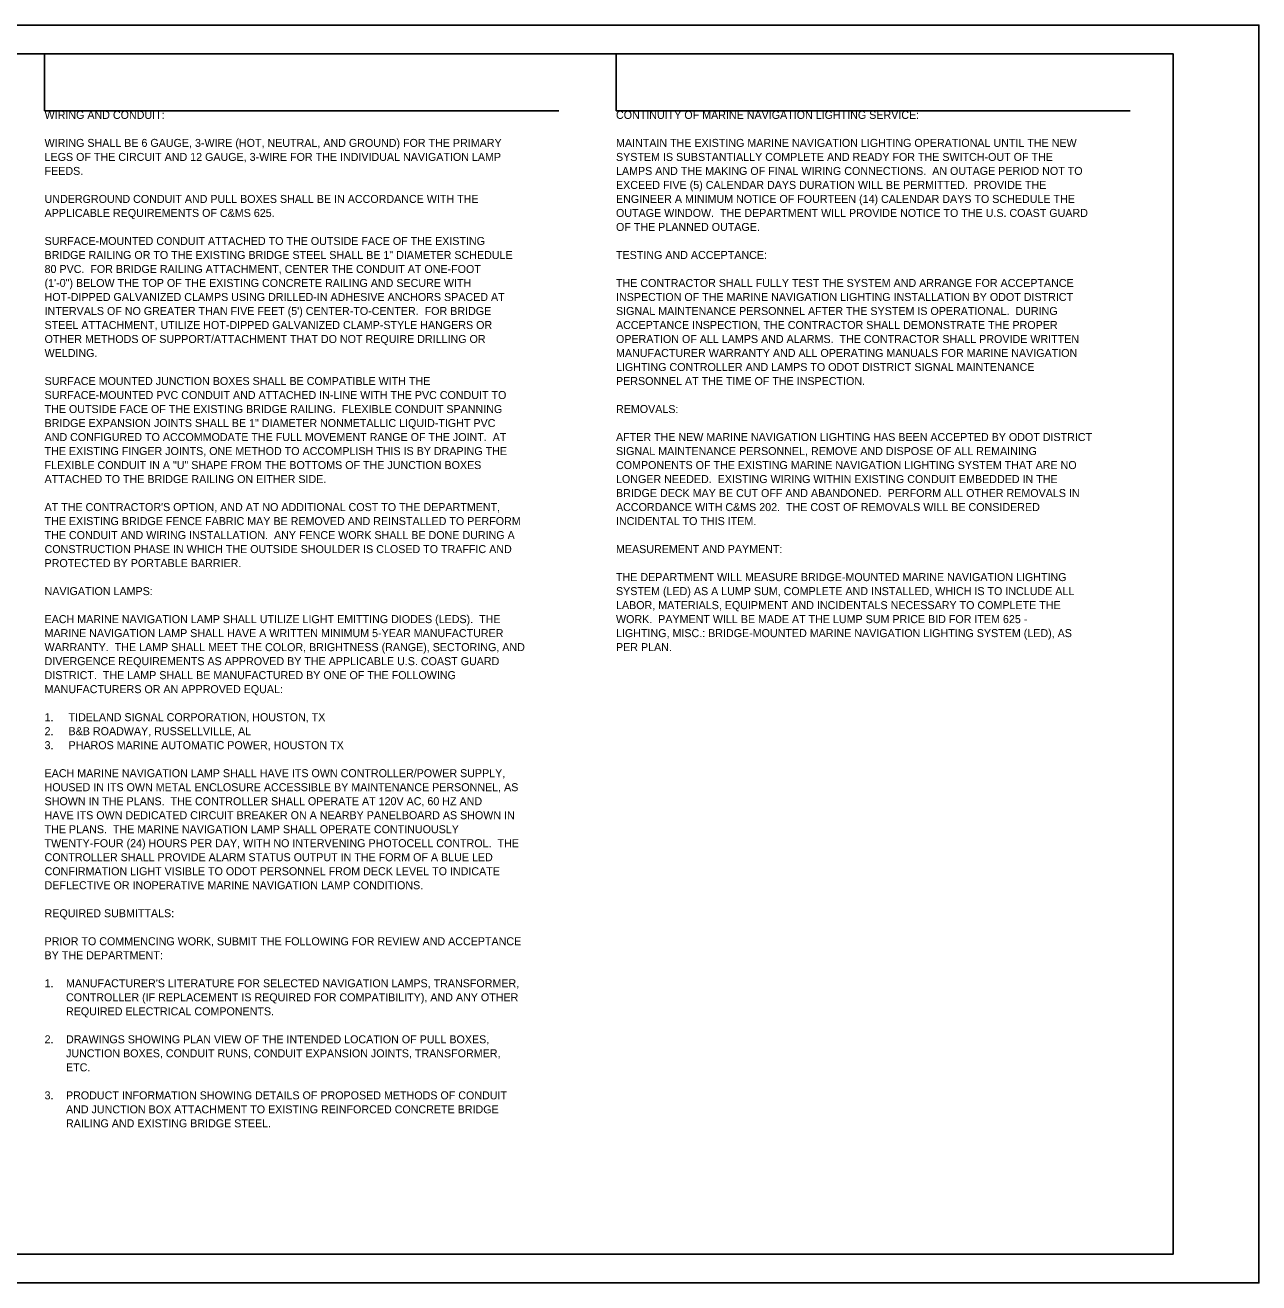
# Model space of a CAD drawing. Extents: x 0 to 34, y 26 to 50.
# Drawn here: x 12.41 to 34, y 26 to 48 of the extents above; entities that cross this region are included whole.
import ezdxf

# ---------------------------------------------------------------- set-up
doc = ezdxf.new("R2010")
doc.units = 0
doc.layers.add('SC_Scratch1', color=7, linetype='Continuous')
doc.layers.add('SH_Text', color=7, linetype='Continuous')

msp = doc.modelspace()

# ---------------------------------------------------------------- linework, layer by layer
at = {"layer": 'SC_Scratch1'}
for p, q in [((12.75, 46.5), (12.75, 47.5)), ((22.75, 46.5), (22.75, 47.5)), ((12.75, 46.5), (21.75, 46.5)), ((22.75, 46.5), (31.75, 46.5))]:
    msp.add_line(p, q, dxfattribs=at)
for points in [[(0, 48), (34, 48), (34, 26), (0, 26)], [(2, 47.5), (32.5, 47.5), (32.5, 26.5), (2, 26.5)]]:
    msp.add_lwpolyline(points, close=True, dxfattribs=at)

# ---------------------------------------------------------------- texts
at = {"layer": 'SH_Text'}
for s, p in [('WIRING AND CONDUIT:', (12.75, 46.36)), ('CONTINUITY OF MARINE NAVIGATION LIGHTING SERVICE:', (22.75, 46.36)), ('WIRING SHALL BE 6 GAUGE, 3-WIRE (HOT, NEUTRAL, AND GROUND) FOR THE PRIMARY ', (12.75, 45.87)), ('MAINTAIN THE EXISTING MARINE NAVIGATION LIGHTING OPERATIONAL UNTIL THE NEW ', (22.75, 45.87)), ('LEGS OF THE CIRCUIT AND 12 GAUGE, 3-WIRE FOR THE INDIVIDUAL NAVIGATION LAMP ', (12.75, 45.625)), ('SYSTEM IS SUBSTANTIALLY COMPLETE AND READY FOR THE SWITCH-OUT OF THE ', (22.75, 45.625)), ('FEEDS.', (12.75, 45.38)), ('LAMPS AND THE MAKING OF FINAL WIRING CONNECTIONS.  AN OUTAGE PERIOD NOT TO ', (22.75, 45.38)), ('EXCEED FIVE (5) CALENDAR DAYS DURATION WILL BE PERMITTED.  PROVIDE THE ', (22.75, 45.135)), ('UNDERGROUND CONDUIT AND PULL BOXES SHALL BE IN ACCORDANCE WITH THE ', (12.75, 44.89)), ('ENGINEER A MINIMUM NOTICE OF FOURTEEN (14) CALENDAR DAYS TO SCHEDULE THE ', (22.75, 44.89)), ('APPLICABLE REQUIREMENTS OF C&MS 625.   ', (12.75, 44.645)), ('OUTAGE WINDOW.  THE DEPARTMENT WILL PROVIDE NOTICE TO THE U.S. COAST GUARD ', (22.75, 44.645)), ('OF THE PLANNED OUTAGE.', (22.75, 44.4)), ('SURFACE-MOUNTED CONDUIT ATTACHED TO THE OUTSIDE FACE OF THE EXISTING ', (12.75, 44.155)), ('BRIDGE RAILING OR TO THE EXISTING BRIDGE STEEL SHALL BE 1" DIAMETER SCHEDULE ', (12.75, 43.91)), ('TESTING AND ACCEPTANCE:', (22.75, 43.91)), ('80 PVC.  FOR BRIDGE RAILING ATTACHMENT, CENTER THE CONDUIT AT ONE-FOOT', (12.75, 43.665)), ('(1\'-0") BELOW THE TOP OF THE EXISTING CONCRETE RAILING AND SECURE WITH ', (12.75, 43.42)), ('THE CONTRACTOR SHALL FULLY TEST THE SYSTEM AND ARRANGE FOR ACCEPTANCE ', (22.75, 43.42)), ('HOT-DIPPED GALVANIZED CLAMPS USING DRILLED-IN ADHESIVE ANCHORS SPACED AT ', (12.75, 43.175)), ('INSPECTION OF THE MARINE NAVIGATION LIGHTING INSTALLATION BY ODOT DISTRICT ', (22.75, 43.175)), ("INTERVALS OF NO GREATER THAN FIVE FEET (5') CENTER-TO-CENTER.  FOR BRIDGE ", (12.75, 42.93)), ('SIGNAL MAINTENANCE PERSONNEL AFTER THE SYSTEM IS OPERATIONAL.  DURING ', (22.75, 42.93)), ('STEEL ATTACHMENT, UTILIZE HOT-DIPPED GALVANIZED CLAMP-STYLE HANGERS OR ', (12.75, 42.685)), ('ACCEPTANCE INSPECTION, THE CONTRACTOR SHALL DEMONSTRATE THE PROPER ', (22.75, 42.685)), ('OTHER METHODS OF SUPPORT/ATTACHMENT THAT DO NOT REQUIRE DRILLING OR ', (12.75, 42.44)), ('OPERATION OF ALL LAMPS AND ALARMS.  THE CONTRACTOR SHALL PROVIDE WRITTEN ', (22.75, 42.44)), ('WELDING.', (12.75, 42.195)), ('MANUFACTURER WARRANTY AND ALL OPERATING MANUALS FOR MARINE NAVIGATION ', (22.75, 42.195)), ('LIGHTING CONTROLLER AND LAMPS TO ODOT DISTRICT SIGNAL MAINTENANCE ', (22.75, 41.95)), ('SURFACE MOUNTED JUNCTION BOXES SHALL BE COMPATIBLE WITH THE ', (12.75, 41.705)), ('PERSONNEL AT THE TIME OF THE INSPECTION.', (22.75, 41.705)), ('SURFACE-MOUNTED PVC CONDUIT AND ATTACHED IN-LINE WITH THE PVC CONDUIT TO ', (12.75, 41.46)), ('THE OUTSIDE FACE OF THE EXISTING BRIDGE RAILING.  FLEXIBLE CONDUIT SPANNING ', (12.75, 41.215)), ('REMOVALS:', (22.75, 41.215)), ('BRIDGE EXPANSION JOINTS SHALL BE 1" DIAMETER NONMETALLIC LIQUID-TIGHT PVC ', (12.75, 40.97)), ('AND CONFIGURED TO ACCOMMODATE THE FULL MOVEMENT RANGE OF THE JOINT.  AT ', (12.75, 40.725)), ('AFTER THE NEW MARINE NAVIGATION LIGHTING HAS BEEN ACCEPTED BY ODOT DISTRICT ', (22.75, 40.725)), ('THE EXISTING FINGER JOINTS, ONE METHOD TO ACCOMPLISH THIS IS BY DRAPING THE ', (12.75, 40.48)), ('SIGNAL MAINTENANCE PERSONNEL, REMOVE AND DISPOSE OF ALL REMAINING ', (22.75, 40.48)), ('FLEXIBLE CONDUIT IN A "U" SHAPE FROM THE BOTTOMS OF THE JUNCTION BOXES ', (12.75, 40.235)), ('COMPONENTS OF THE EXISTING MARINE NAVIGATION LIGHTING SYSTEM THAT ARE NO ', (22.75, 40.235)), ('ATTACHED TO THE BRIDGE RAILING ON EITHER SIDE.', (12.75, 39.99)), ('LONGER NEEDED.  EXISTING WIRING WITHIN EXISTING CONDUIT EMBEDDED IN THE ', (22.75, 39.99)), ('BRIDGE DECK MAY BE CUT OFF AND ABANDONED.  PERFORM ALL OTHER REMOVALS IN ', (22.75, 39.745)), ("AT THE CONTRACTOR'S OPTION, AND AT NO ADDITIONAL COST TO THE DEPARTMENT, ", (12.75, 39.5)), ('ACCORDANCE WITH C&MS 202.  THE COST OF REMOVALS WILL BE CONSIDERED ', (22.75, 39.5)), ('THE EXISTING BRIDGE FENCE FABRIC MAY BE REMOVED AND REINSTALLED TO PERFORM ', (12.75, 39.255)), ('INCIDENTAL TO THIS ITEM.', (22.75, 39.255)), ('THE CONDUIT AND WIRING INSTALLATION.  ANY FENCE WORK SHALL BE DONE DURING A ', (12.75, 39.01)), ('CONSTRUCTION PHASE IN WHICH THE OUTSIDE SHOULDER IS CLOSED TO TRAFFIC AND ', (12.75, 38.765)), ('MEASUREMENT AND PAYMENT:', (22.75, 38.765)), ('PROTECTED BY PORTABLE BARRIER.', (12.75, 38.52)), ('THE DEPARTMENT WILL MEASURE BRIDGE-MOUNTED MARINE NAVIGATION LIGHTING ', (22.75, 38.275)), ('NAVIGATION LAMPS:', (12.75, 38.03)), ('SYSTEM (LED) AS A LUMP SUM, COMPLETE AND INSTALLED, WHICH IS TO INCLUDE ALL ', (22.75, 38.03)), ('LABOR, MATERIALS, EQUIPMENT AND INCIDENTALS NECESSARY TO COMPLETE THE ', (22.75, 37.785)), ('EACH MARINE NAVIGATION LAMP SHALL UTILIZE LIGHT EMITTING DIODES (LEDS).  THE ', (12.75, 37.54)), ('WORK.  PAYMENT WILL BE MADE AT THE LUMP SUM PRICE BID FOR ITEM 625 - ', (22.75, 37.54)), ('MARINE NAVIGATION LAMP SHALL HAVE A WRITTEN MINIMUM 5-YEAR MANUFACTURER ', (12.75, 37.295)), ('LIGHTING, MISC.: BRIDGE-MOUNTED MARINE NAVIGATION LIGHTING SYSTEM (LED), AS ', (22.75, 37.295)), ('WARRANTY.  THE LAMP SHALL MEET THE COLOR, BRIGHTNESS (RANGE), SECTORING, AND ', (12.75, 37.05)), ('PER PLAN.', (22.75, 37.05)), ('DIVERGENCE REQUIREMENTS AS APPROVED BY THE APPLICABLE U.S. COAST GUARD ', (12.75, 36.805)), ('DISTRICT.  THE LAMP SHALL BE MANUFACTURED BY ONE OF THE FOLLOWING ', (12.75, 36.56)), ('MANUFACTURERS OR AN APPROVED EQUAL:', (12.75, 36.315)), ('1.', (12.75, 35.825)), ('TIDELAND SIGNAL CORPORATION, HOUSTON, TX', (13.17, 35.825)), ('2.', (12.75, 35.58)), ('B&B ROADWAY, RUSSELLVILLE, AL', (13.17, 35.58)), ('3.', (12.75, 35.335)), ('PHAROS MARINE AUTOMATIC POWER, HOUSTON TX', (13.17, 35.335)), ('EACH MARINE NAVIGATION LAMP SHALL HAVE ITS OWN CONTROLLER/POWER SUPPLY, ', (12.75, 34.845)), ('HOUSED IN ITS OWN METAL ENCLOSURE ACCESSIBLE BY MAINTENANCE PERSONNEL, AS ', (12.75, 34.6)), ('SHOWN IN THE PLANS.  THE CONTROLLER SHALL OPERATE AT 120V AC, 60 HZ AND ', (12.75, 34.355)), ('HAVE ITS OWN DEDICATED CIRCUIT BREAKER ON A NEARBY PANELBOARD AS SHOWN IN ', (12.75, 34.11)), ('THE PLANS.  THE MARINE NAVIGATION LAMP SHALL OPERATE CONTINUOUSLY ', (12.75, 33.865)), ('TWENTY-FOUR (24) HOURS PER DAY, WITH NO INTERVENING PHOTOCELL CONTROL.  THE ', (12.75, 33.62)), ('CONTROLLER SHALL PROVIDE ALARM STATUS OUTPUT IN THE FORM OF A BLUE LED ', (12.75, 33.375)), ('CONFIRMATION LIGHT VISIBLE TO ODOT PERSONNEL FROM DECK LEVEL TO INDICATE ', (12.75, 33.13)), ('DEFLECTIVE OR INOPERATIVE MARINE NAVIGATION LAMP CONDITIONS.', (12.75, 32.885)), ('REQUIRED SUBMITTALS:', (12.75, 32.395)), ('PRIOR TO COMMENCING WORK, SUBMIT THE FOLLOWING FOR REVIEW AND ACCEPTANCE ', (12.75, 31.905)), ('BY THE DEPARTMENT:', (12.75, 31.66)), ('1.', (12.75, 31.17)), ("MANUFACTURER'S LITERATURE FOR SELECTED NAVIGATION LAMPS, TRANSFORMER, ", (13.125, 31.17)), ('CONTROLLER (IF REPLACEMENT IS REQUIRED FOR COMPATIBILITY), AND ANY OTHER ', (13.125, 30.925)), ('REQUIRED ELECTRICAL COMPONENTS.', (13.125, 30.68)), ('2.', (12.75, 30.19)), ('DRAWINGS SHOWING PLAN VIEW OF THE INTENDED LOCATION OF PULL BOXES, ', (13.125, 30.19)), ('JUNCTION BOXES, CONDUIT RUNS, CONDUIT EXPANSION JOINTS, TRANSFORMER, ', (13.125, 29.945)), ('ETC.', (13.125, 29.7)), ('3.', (12.75, 29.21)), ('PRODUCT INFORMATION SHOWING DETAILS OF PROPOSED METHODS OF CONDUIT ', (13.125, 29.21)), ('AND JUNCTION BOX ATTACHMENT TO EXISTING REINFORCED CONCRETE BRIDGE ', (13.125, 28.965)), ('RAILING AND EXISTING BRIDGE STEEL.', (13.125, 28.72))]:
    msp.add_text(s, height=0.14, dxfattribs=at).set_placement(p)

doc.saveas('drawing.dxf')
